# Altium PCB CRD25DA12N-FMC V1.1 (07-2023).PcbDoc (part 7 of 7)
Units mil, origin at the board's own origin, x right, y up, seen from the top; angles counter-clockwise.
Board outline 8000 x 8000 mil, 6 copper layers (Top Layer, Layer 2, Layer 3, Layer 4, Layer 5, Bottom Layer), stack 91 mil thick; 542 components, 315 nets, 1585 pads, 558 vias.
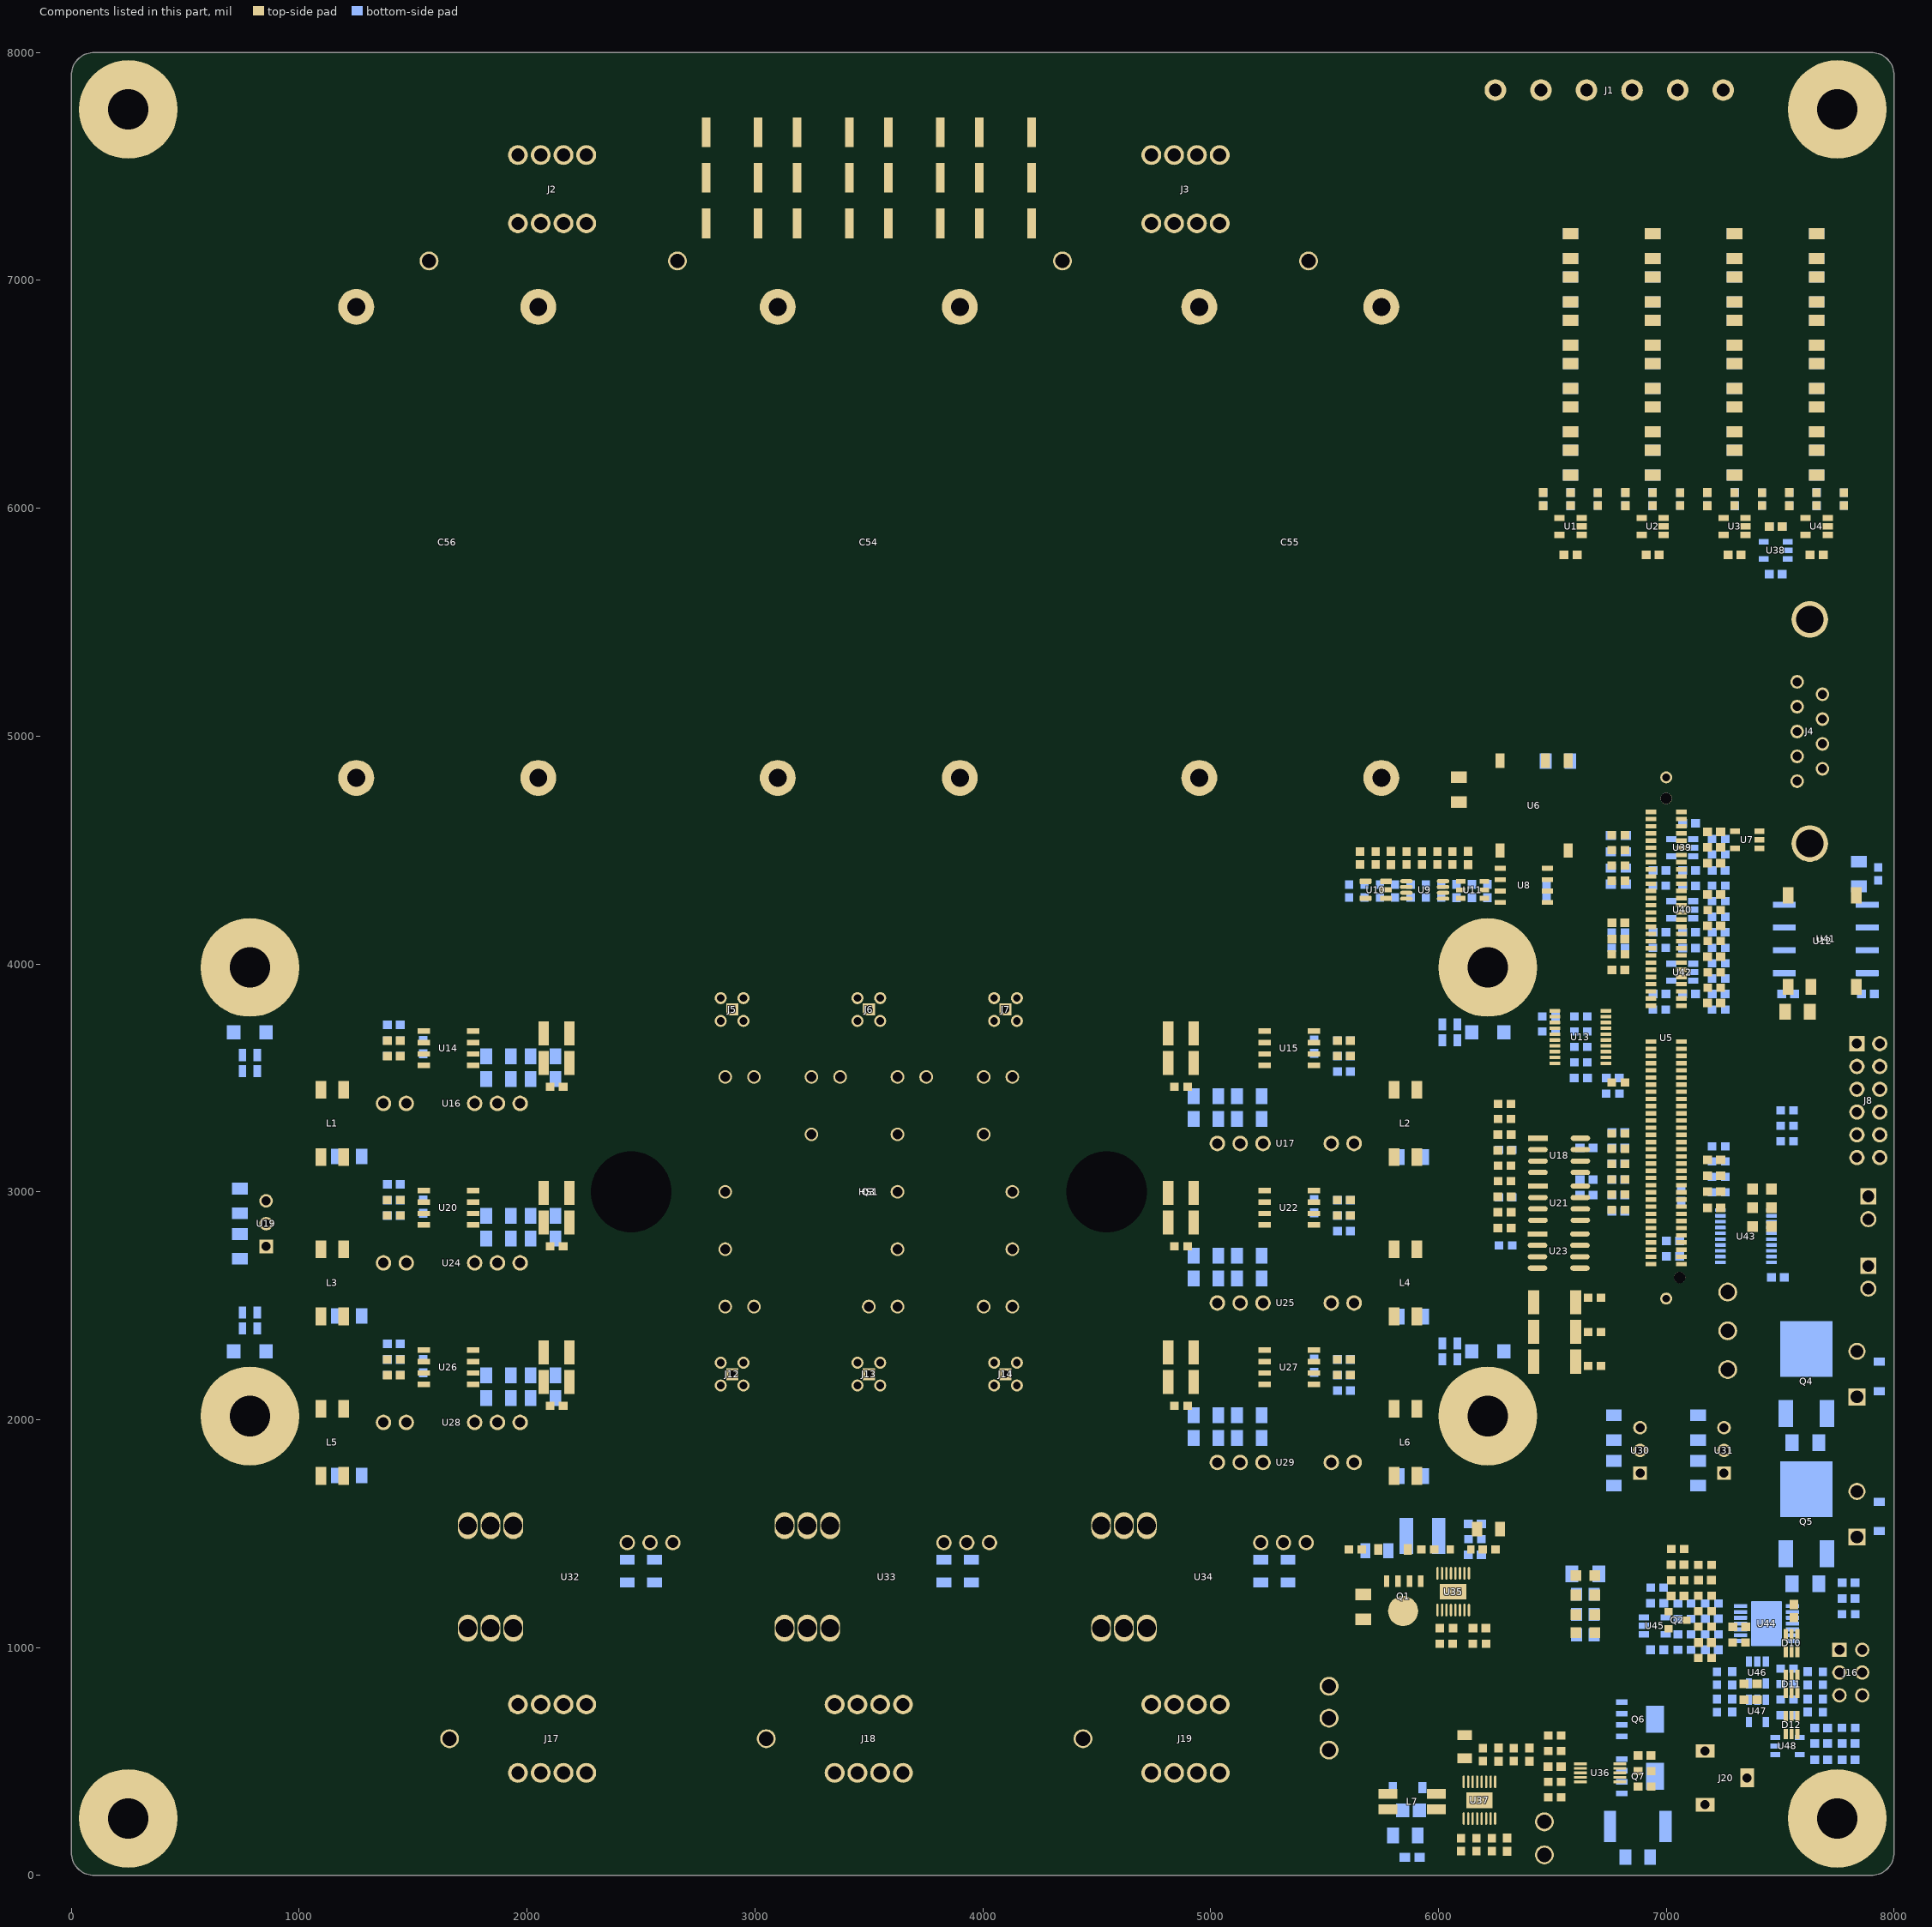
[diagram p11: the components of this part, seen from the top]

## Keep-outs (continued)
Layer 4:
  circle w10: c5040,7550 r200
  circle w10: c4740,7550 r200
  circle w10: c4740,7250 r200
  circle w10: c5040,7250 r200
  circle w10: c2850,3850 r190
  circle w10: c2850,3503.94 r190
  circle w10: c4150,3850 r190
  circle w10: c4150,3503.94 r190
  circle w10: c6065,7280 r192
  circle w10: c5670,4820 r235
  region: 4625,1490 4585,1490 4585,1420 4625,1420
  rectangle: 4265,985 4305,1055
  rectangle: 4535,7262.91 5245,7802.91
  region: 4555,7755 4515,7755 4515,7685 4555,7685
  rectangle: 4735,7044.79 5040,7077.21
  region: 5220,7750 5220,7710 5290,7710 5290,7750
  rectangle: 7724.19,4275 7783.78,4418.29
  region: 1415.31,1894.07 1415.31,1854.07 1485.31,1854.07 1485.31,1894.07
  rectangle: 2541.38,1103.21 2581.38,1173.21
  rectangle: 2800,260 2840,330
  rectangle: 3920,260 3960,330
  rectangle: 3931.38,1103.21 3971.38,1173.21
  rectangle: 4195,255 4235,325
  rectangle: 5317.18,1103.22 5357.18,1173.22
  rectangle: 5305,260 5345,330
  rectangle: 7455.41,5521.71 7515,5665
  rectangle: 7455.79,4364.18 7515.39,4507.46
  rectangle: 7734.19,3725 7793.78,3868.29
  rectangle: 7524,30 7654,255
  rectangle: 7754,331.5 7970,476.5
  rectangle: 7825,40 7960,165
  region: 4890,1395 4850,1395 4850,1325 4890,1325
  region: 4895,990 4895,1030 4825,1030 4825,990
  region: 3570,985 3570,1025 3500,1025 3500,985
  rectangle: 2920,980 2960,1050
  region: 2180,990 2180,1030 2110,1030 2110,990
  rectangle: 1530,985 1570,1055
  region: 1530,1665 1530,1625 1600,1625 1600,1665
  rectangle: 5930,4819.65 6047.21,4990.03
  rectangle: 5670,4965 6260,5060.38
  rectangle: 2656.25,3503.94 4345.42,3875.51
  rectangle: 2850,3310.19 4175.51,4045.42
  rectangle: 2335,3170 2375,3240
  rectangle: 1980,3170 2345,3295
  region: 4545,3165 4545,3205 4475,3205 4475,3165
  rectangle: 4530,3150 4735,3945
  rectangle: 2270.5,3210 2345.5,3845
  region: 5875,7755 5835,7755 5835,7685 5875,7685
  rectangle: 5867.58,7280 6120,7755
  rectangle: 6065,7082.58 6250,7755
  rectangle: 5630,4880 5705,5050.38
  rectangle: 5565,4860 5640,5030.38
  rectangle: 5530,4835 5605,5005.38
  rectangle: 5455,4750 5530,4920.38
  rectangle: 5495,4800 5570,4970.38
  rectangle: 6005,7095 6080,7265.38
  rectangle: 5945,7125 6020,7295.38
  region: 6250,7095 6210,7095 6210,7025 6250,7025
  region: 6255,5050 6255,5090 6185,5090 6185,5050
  rectangle: 5905,7165 5980,7335.38
  region: 4610,4020 4570,4020 4570,3950 4610,3950
  region: 4580,3990 4540,3990 4540,3920 4580,3920
  rectangle: 4659.34,3790 5435,4070.5
  region: 4675,4065 4635,4065 4635,3995 4675,3995
  region: 4635,4045 4595,4045 4595,3975 4635,3975
  rectangle: 1095,3856 2195,3971
  rectangle: 2165,3855 2240,3960
  region: 2290,3930 2215,3930 2215,3825 2290,3825
  region: 2270,3950 2195,3950 2195,3845 2270,3845
  region: 2320,3890 2245,3890 2245,3785 2320,3785
  region: 2310,3910 2235,3910 2235,3805 2310,3805
  region: 730,7745 730,7705 800,7705 800,7745
  rectangle: 5430,3975 5530,4820
  lines w10: 485,1750 ccw(c560,1750) 560,1675 ; 485.01,3653.79 cw(c560,3655) 558.79,3729.99 ; 753.02,4471.01 ccw(c878,4469) 875.99,4344.02 ; 755.02,7597.41 cw(c905,7595) 907.41,7744.98 ; 1147.85,4063.45 ccw(c1270,4090) 1267.99,3965.02 ; 1325,1675 ccw(c1325,1750) 1400,1750 ; 1400,1843.79 cw(c1474.99,1845) 1473.78,1919.99 ; 1503.79,3730.03 cw(c1505,3655.04) 1579.99,3656.25 ; 1506.21,1920.05 ccw(c1505,1995.04) 1579.99,1996.25 ; 1540,1145 ccw(c1690,1145) 1690,995 ; 1540.02,1512.41 cw(c1690,1510) 1692.41,1659.98 ; 1729.2,1969.19 ccw(c1779.2,1969.99) 1780,1920 ; 1729.2,2669.19 ccw(c1779.2,2669.99) 1780,2620 ; 1729.2,3369.19 ccw(c1779.2,3369.99) 1780,3320 ; 1730.01,2334.2 cw(c1780,2335) 1779.2,2384.99 ; 1730.01,3034.2 cw(c1780,3035) 1779.2,3084.99 ; 1730.01,3734.2 cw(c1780,3735) 1779.2,3784.99 ; 2020,995 ccw(c2020,1145) 2170,1145 ; 2124.95,3936.6 cw(c2208,3834) 2268.9,3716.89 ; 2199.2,2384.99 cw(c2200,2335) 2249.99,2335.8 ; 2199.2,3084.99 cw(c2200,3035) 2249.99,3035.8 ; 2199.2,3784.99 cw(c2200,3735) 2249.99,3735.8 ; 2200.8,1920.01 ccw(c2200,1970) 2249.99,1970.8 ; 2200.8,2620.01 ccw(c2200,2670) 2249.99,2670.8 ; 2200.8,3320.01 ccw(c2200,3370) 2249.99,3370.8 ; 2340.02,3332.41 ccw(c2490,3330) 2487.59,3180.02 ; 2380.01,1443.79 cw(c2455,1445) 2453.79,1519.99 ; 2544.2,1184.99 cw(c2545,1135) 2594.99,1135.8 ; 2595.01,118.79 ccw(c2670,120) 2671.21,45.01 ; 2703.79,1519.99 cw(c2705,1445) 2779.99,1446.21 ; 2780.01,313.79 ccw(c2855,315) 2856.21,240.01 ; 2858.39,2640 ccw(c2860,2739.99) 2959.99,2738.38 ; 2861.61,2849.99 cw(c2860,2750) 2959.99,2748.39 ; 2930,1145 ccw(c3080,1145) 3080,995 ; 3410,995 ccw(c3410,1145) 3560,1145 ; 3614.3,2640 ccw(c3615.91,2739.99) 3715.89,2738.38 ; 3617.51,2849.99 cw(c3615.91,2750) 3715.89,2748.39 ; 3770.01,1443.79 cw(c3845,1445) 3843.79,1519.99 ; 3911.21,240.01 ccw(c3910,315) 3984.99,316.21 ; 3934.2,1184.99 cw(c3935,1135) 3984.99,1135.8 ; 4041.62,2741.6 ccw(c4141.61,2739.99) 4140,2640 ; 4041.62,2751.62 cw(c4141.61,2750.01) 4143.22,2850 ; 4093.79,1519.99 cw(c4095,1445) 4169.99,1446.21 ; 4170.01,313.79 ccw(c4245,315) 4246.21,240.01 ; 4275,1145 ccw(c4425,1145) 4425,995 ; 4382.59,3180.02 ccw(c4385,3330) 4534.98,3327.59 ; 4394.41,7744.98 cw(c4392,7595) 4541.98,7592.59 ; 4535,1535 ccw(c4685,1535) 4685,1385 ; 4535.02,3942.03 cw(c4660,3940.02) 4662.01,4065 ; 4735,995 ccw(c4735,1145) 4885,1145 ; 4735,1385 cw(c4735,1235) 4885,1235 ; 4739.2,2325.81 cw(c4789.2,2325.01) 4790,2375 ; 4739.2,3025.81 cw(c4789.2,3025.01) 4790,3075 ; 4739.2,3725.81 cw(c4789.2,3725.01) 4790,3775 ; 4740.81,1820.8 ccw(c4790.8,1819.99) 4790,1770 ; 4740.81,2520.8 ccw(c4790.8,2519.99) 4790,2470 ; 4740.81,3220.8 ccw(c4790.8,3219.99) 4790,3170 ; 5104.2,2375.01 cw(c5104.2,2325.01) 5151.18,2342.11 ; 5104.2,3075.01 cw(c5104.2,3025.01) 5151.18,3042.11 ; 5104.2,3775.01 cw(c5104.2,3725.01) 5151.18,3742.11 ; 5160.01,1443.79 cw(c5235,1445) 5233.79,1519.99 ; 5220,1770 ccw(c5220.8,1819.99) 5270.8,1819.19 ; 5220,2470 ccw(c5220.8,2519.99) 5270.8,2519.19 ; 5220,3170 ccw(c5220.8,3219.99) 5270.8,3219.19 ; 5232.94,2313.3 cw(c5220,2265) 5270,2265 ; 5232.94,3013.3 cw(c5220,2965) 5270,2965 ; 5232.94,3713.3 cw(c5220,3665) 5270,3665 ; 5240.02,7597.41 cw(c5390,7595) 5392.41,7744.98 ; 5296.21,240.01 ccw(c5295,315) 5369.99,316.21 ; 5307.99,4065.02 ccw(c5310,4190) 5434.98,4187.99 ; 5320,1185 cw(c5320.8,1135.01) 5370.8,1135.81 ; 5320.81,1519.2 ccw(c5320.01,1569.2) 5370,1570 ; 5370,1575 cw(c5419.99,1575.8) 5419.19,1625.8 ; 5420.01,1733.79 ccw(c5495,1735) 5496.21,1660.01 ; 5420.01,3693.79 cw(c5495,3695) 5493.79,3769.99 ; 5580.01,4280.8 ccw(c5630,4279.99) 5629.2,4230 ; 5580.01,4475.8 cw(c5630,4475) 5630.8,4524.99 ; 5724.41,7744.98 cw(c5722,7595) 5871.98,7592.59 ; 5873.79,1624.99 cw(c5875,1550) 5949.99,1551.21 ; 5876.21,45.01 ccw(c5875,120) 5949.99,121.21 ; 5965.01,118.79 ccw(c6040,120) 6041.21,45.01 ; 5965.01,1548.79 cw(c6040,1550) 6038.79,1624.99 ; 6000,4524.53 ccw(c6000.8,4574.52) 6050.8,4573.71 ; 6050.01,4880.8 cw(c6100,4880) 6100.8,4929.99 ; 6088.79,3769.99 cw(c6090,3695) 6164.99,3696.21 ; 6091.21,1660.01 ccw(c6090,1735) 6164.99,1736.21 ; 6092.59,5055.02 ccw(c6095,5205) 6244.98,5202.59 ; 6097.41,7086.98 cw(c6095,6937) 6244.98,6934.59 ; 6111.21,1625.01 ccw(c6110,1700) 6184.99,1701.21 ; 6185.01,2308.79 ccw(c6260,2310) 6261.21,2235.01 ; 6185.01,3693.79 cw(c6260,3695) 6258.79,3769.99 ; 6186.22,1723.8 cw(c6261.21,1725.01) 6260,1800 ; 6249.2,4230.01 ccw(c6250,4280) 6299.99,4279.2 ; 6250.8,4929.99 cw(c6250,4880) 6299.99,4879.2 ; 6331.21,3770.01 ccw(c6330,3845) 6404.99,3846.21 ; 6405.01,6103.79 cw(c6480,6105) 6478.79,6179.99 ; 6531.21,45.01 ccw(c6530,120) 6604.99,121.21 ; 6605.01,118.79 ccw(c6680,120) 6681.21,45.01 ; 6605,530 cw(c6680,530) 6680,605 ; 7315,605 cw(c7315,530) 7390,530 ; 7316.21,45.01 ccw(c7315,120) 7389.99,121.21 ccw(c7464.98,122.41) 7466.19,47.42 ; 7335,1945 ccw(c7360,1945) 7360,1920 ; 7335,1970 cw(c7360,1970) 7360,1995 ; 7420,580 ccw(c7445,580) 7445,555 ; 7420,685 cw(c7445,685) 7445,710 ; 7435.01,4418.79 ccw(c7510,4420) 7511.21,4345.01 ; 7435.01,5608.79 cw(c7510,5610) 7508.79,5684.99 ; 7456.21,47.42 ccw(c7455,122.41) 7529.99,123.62 ; 7500,710 ccw(c7500,735) 7525,735 ; 7500,1920 cw(c7500,1895) 7525,1895 ; 7535.01,4686.79 ccw(c7610,4688) 7611.21,4613.01 ; 7535.01,5351.79 cw(c7610,5353) 7608.79,5427.99 ; 7545,1995 cw(c7545,1970) 7570,1970 ; 7570,650 ccw(c7595,650) 7595,625 ; 7605,555 ccw(c7605,580) 7630,580 ; 7605,625 cw(c7605,600) 7630,600 ; 7633.79,4344.99 cw(c7635,4270) 7709.99,4271.21 ; 7710.01,3778.79 ccw(c7785,3780) 7786.21,3705.01 ; 7710.01,4491.12 ccw(c7765,4492) 7765.88,4437.01 ; 7715.01,5523.79 cw(c7790,5525) 7788.79,5599.99 ; 7749.12,4439.99 cw(c7750,4385) 7804.99,4385.88 ; 7805.01,3889.2 ccw(c7855,3890) 7855.8,3840.01 ; 7878.79,5599.99 cw(c7880,5525) 7954.99,5526.21 ; 7878.79,6179.99 cw(c7880,6105) 7954.99,6106.21 ; 7881.21,469.93 ccw(c7880,544.92) 7954.99,546.13 ; 7881.21,5685.01 ccw(c7880,5760) 7954.99,5761.21 ; 7883.79,3704.99 cw(c7885,3630) 7959.99,3631.21 ; 7905.81,3839.2 ccw(c7905.01,3889.2) 7955,3890
Layer 5:
  circle w10: c1960,7550 r200
  circle w10: c1960,7250 r200
  circle w10: c2260,7550 r200
  circle w10: c2260,7250 r200
  circle w10: c2850,3850 r190
  circle w10: c2850,3503.94 r190
  circle w10: c4150,3503.94 r190
  circle w10: c4150,3850 r190
  circle w10: c6065,7280 r192
  rectangle: 1625,3460 1725,3808.71
  region: 1132.42,4041.06 1072.42,4041.06 1072.42,3826.06 1132.42,3826.06
  region: 1843.21,6875 1843.21,7180 1810.79,7180 1810.79,6875
  region: 2289.21,6875 2289.21,7180 2256.79,7180 2256.79,6875
  region: 1601.27,6999.57 1359.3,6813.89 1428.03,6724.33 1670,6910
  region: 1445.61,7242.78 1171.71,7108.6 1221.38,7007.22 1495.28,7141.4
  rectangle: 3237.88,3061.97 4005,3330
  rectangle: 1755,7262.91 2465,7802.91
  region: 1775,7755 1735,7755 1735,7685 1775,7685
  region: 2440,7750 2440,7710 2510,7710 2510,7750
  rectangle: 1955,7044.79 2260,7077.21
  rectangle: 7734.19,3725 7793.78,3868.29
  rectangle: 7455.79,4364.18 7515.39,4507.46
  region: 1415.31,1894.07 1415.31,1854.07 1485.31,1854.07 1485.31,1894.07
  rectangle: 5317.18,1103.22 5357.18,1173.22
  rectangle: 5365,1545 5405,1615
  rectangle: 5305,260 5345,330
  rectangle: 4195,255 4235,325
  rectangle: 7455.41,5521.71 7515,5665
  rectangle: 7724.19,4275 7783.78,4418.29
  rectangle: 2541.38,1103.21 2581.38,1173.21
  rectangle: 3931.38,1103.21 3971.38,1173.21
  rectangle: 2800,260 2840,330
  rectangle: 3920,260 3960,330
  rectangle: 5990,3975 6080,4120
  rectangle: 7524,30 7654,255
  rectangle: 7754,331.5 7970,476.5
  rectangle: 7825,40 7960,165
  region: 4310,1625 4310,1585 4380,1585 4380,1625
  region: 4955,1630 4915,1630 4915,1560 4955,1560
  rectangle: 4315,325 4355,395
  region: 5250,330 5250,370 5180,370 5180,330
  region: 2920,1630 2920,1590 2990,1590 2990,1630
  region: 3565,1635 3525,1635 3525,1565 3565,1565
  rectangle: 2925,325 2965,395
  region: 3860,330 3860,370 3790,370 3790,330
  region: 2470,330 2470,370 2400,370 2400,330
  rectangle: 1535,325 1575,395
  region: 2175,1635 2135,1635 2135,1565 2175,1565
  region: 1530,1630 1530,1590 1600,1590 1600,1630
  rectangle: 5342.08,3758.41 5401.67,3901.7
  rectangle: 5260.61,3920 5485,3995
  rectangle: 5385.61,4025 5580,4078.37
  rectangle: 5445.61,4060 5635,4113.37
  rectangle: 5360,3835 5429.94,4055
  rectangle: 5415,4105 5550,4125
  rectangle: 5380,3985 5545,4088.29
  rectangle: 5304.19,3670 5363.78,3813.29
  rectangle: 2656.25,3503.94 4345.42,3875.51
  rectangle: 2850,3310.19 4175.51,4045.42
  region: 730,7745 730,7705 800,7705 800,7745
  rectangle: 2270.5,3225 2345.5,3845
  region: 2320,3890 2245,3890 2245,3785 2320,3785
  region: 2270,3950 2195,3950 2195,3845 2270,3845
  rectangle: 1095,3856 2195,3971
  region: 2310,3910 2235,3910 2235,3805 2310,3805
  region: 2290,3930 2215,3930 2215,3825 2290,3825
  rectangle: 2165,3855 2240,3960
  region: 875,4325 705,4325 705,4255 875,4255
  region: 980,4275 810,4275 810,4205 980,4205
  region: 1110,4115 1050,4115 1050,3900 1110,3900
  region: 1060,4200 1000,4200 1000,3985 1060,3985
  region: 1000,4255 940,4255 940,4155 1000,4155
  rectangle: 1150,3800 1725,3894.7
  rectangle: 1780,3090 2345,3295
  region: 5875,7755 5835,7755 5835,7685 5875,7685
  rectangle: 5867.58,7280 6120,7755
  rectangle: 6065,7082.58 6250,7755
  rectangle: 5945,7125 6020,7295.38
  rectangle: 5905,7165 5980,7335.38
  rectangle: 6005,7095 6080,7265.38
  region: 6250,7095 6210,7095 6210,7025 6250,7025
  rectangle: 2755,3340 2855,3465
  rectangle: 2675,3430 2775,3555
  rectangle: 2705,3380 2805,3505
  region: 2736.06,4000.08 2736.06,3900.08 2861.06,3900.08 2861.06,4000.08
  region: 2786.06,4030.08 2786.06,3930.08 2911.06,3930.08 2911.06,4030.08
  region: 2696.06,3950.08 2696.06,3850.08 2821.06,3850.08 2821.06,3950.08
  region: 4295,3505 4195,3505 4195,3380 4295,3380
  region: 4325,3555 4225,3555 4225,3430 4325,3430
  region: 4245,3465 4145,3465 4145,3340 4245,3340
  region: 4178.94,3950.08 4178.94,3850.08 4303.94,3850.08 4303.94,3950.08
  region: 4088.94,4030.08 4088.94,3930.08 4213.94,3930.08 4213.94,4030.08
  region: 4138.94,4000.08 4138.94,3900.08 4263.94,3900.08 4263.94,4000.08
  rectangle: 2335,3170 2375,3240
  rectangle: 2270,2870 2340,3122.06
  rectangle: 5590,4537.97 6040,4680
  rectangle: 5650,4132.97 6070,4215
  rectangle: 5895,4568.58 6044.8,4925
  rectangle: 6060,4933.58 6390,5085
  rectangle: 5425,4120 5568.9,4520
  rectangle: 5545,4115 5810,4185
  rectangle: 5925,4930 6345,5007.03
  rectangle: 5445,4497.97 5540,4580
  rectangle: 5997.36,4986.83 6390,5063.86
  rectangle: 5476.9,4548.76 5571.9,4630.79
  rectangle: 5530,4582.97 5625,4665
  rectangle: 5850,4645 5920,4722.03
  rectangle: 6190,5050 6260,5127.03
  rectangle: 4530,3070 4745,3945
  region: 4580,3990 4540,3990 4540,3920 4580,3920
  region: 4610,4020 4570,4020 4570,3950 4610,3950
  region: 4635,4045 4595,4045 4595,3975 4635,3975
  region: 4675,4065 4635,4065 4635,3995 4675,3995
  rectangle: 4659.34,3790 5370,4070.5
  lines w10: 433.64,3984.25 cw(c783.46,3984.25) 1133.29,3984.25 ; 485,1750 ccw(c560,1750) 560,1675 ; 485.01,3653.79 cw(c560,3655) 558.79,3729.99 ; 755.02,4450.01 ccw(c880,4448) 877.99,4323.02 ; 755.02,7597.41 cw(c905,7595) 907.41,7744.98 ; 1122.85,4063.45 ccw(c1245,4090) 1242.99,3965.02 ; 1325,1675 ccw(c1325,1750) 1400,1750 ; 1400,1843.79 cw(c1474.99,1845) 1473.78,1919.99 ; 1502.78,3729.23 cw(c1503.99,3654.24) 1578.98,3655.45 ; 1505.19,1919.25 ccw(c1503.99,1994.24) 1578.98,1995.45 ; 1540.02,487.41 ccw(c1690,485) 1687.59,335.02 ; 1540.02,1477.41 cw(c1690,1475) 1692.41,1624.98 ; 1614.41,7744.98 cw(c1612,7595) 1761.98,7592.59 ; 1730,2167 ccw(c1780,2167) 1762.9,2120.02 ; 1730,2265 cw(c1780,2265) 1780,2315 1805,2315 ; 1730,2867 ccw(c1780,2867) 1762.9,2820.02 ; 1730,2965 cw(c1780,2965) 1780,3015 1805,3015 ; 1730,3567 ccw(c1780,3567) 1762.9,3520.02 ; 1730,3665 cw(c1780,3665) 1780,3715 1805,3715 ; 1781.32,2069.24 ccw(c1828.3,2052.14) 1790,2020 ; 1781.32,2769.24 ccw(c1828.3,2752.14) 1790,2720 ; 1781.32,3469.24 ccw(c1828.3,3452.14) 1790,3420 ; 1804.2,1969.19 ccw(c1854.2,1969.99) 1855,1920 ; 1804.2,2669.19 ccw(c1854.2,2669.99) 1855,2620 ; 1804.2,3369.19 ccw(c1854.2,3369.99) 1855,3320 ; 1849.01,2334.2 cw(c1899,2335) 1898.2,2384.99 ; 1849.01,3034.2 cw(c1899,3035) 1898.2,3084.99 ; 1849.01,3734.2 cw(c1899,3735) 1898.2,3784.99 ; 2022.41,1624.98 cw(c2020,1475) 2169.98,1472.59 ; 2124.95,3936.6 cw(c2208,3834) 2268.9,3716.89 ; 2199.2,2384.99 cw(c2200,2335) 2249.99,2335.8 ; 2199.2,3084.99 cw(c2200,3035) 2249.99,3035.8 ; 2199.2,3784.99 cw(c2200,3735) 2249.99,3735.8 ; 2200.8,1920.01 ccw(c2200,1970) 2249.99,1970.8 ; 2200.8,2620.01 ccw(c2200,2670) 2249.99,2670.8 ; 2200.8,3320.01 ccw(c2200,3370) 2249.99,3370.8 ; 2285,6947 cw(c2435,6947) 2360,7076.9 ; 2307.59,335.02 ccw(c2310,485) 2459.98,482.59 ; 2340.02,3332.41 ccw(c2490,3330) 2487.59,3180.02 ; 2380.01,1443.79 cw(c2455,1445) 2453.79,1519.99 ; 2460.02,7597.41 cw(c2610,7595) 2612.41,7744.98 ; 2544.2,1184.99 cw(c2545,1135) 2594.99,1135.8 ; 2595.01,118.79 ccw(c2670,120) 2671.21,45.01 ; 2633.02,3052.01 ccw(c2758,3050) 2755.99,2925.02 ; 2703.79,1519.99 cw(c2705,1445) 2779.99,1446.21 ; 2780.01,313.79 ccw(c2855,315) 2856.21,240.01 ; 2930.02,487.41 ccw(c3080,485) 3077.59,335.02 ; 2930.02,1477.41 cw(c3080,1475) 3082.41,1624.98 ; 2986.79,3315.99 cw(c2988,3241) 3062.99,3242.21 ; 3412.41,1624.98 cw(c3410,1475) 3559.98,1472.59 ; 3697.59,335.02 ccw(c3700,485) 3849.98,482.59 ; 3770.01,1443.79 cw(c3845,1445) 3843.79,1519.99 ; 3911.21,240.01 ccw(c3910,315) 3984.99,316.21 ; 3934.2,1184.99 cw(c3935,1135) 3984.99,1135.8 ; 4093.79,1519.99 cw(c4095,1445) 4169.99,1446.21 ; 4170.01,313.79 ccw(c4245,315) 4246.21,240.01 ; 4189,3265 cw(c4264,3265) 4238.35,3335.48 ; 4244.01,2925.02 ccw(c4242,3050) 4366.98,3052.01 ; 4320.02,487.41 ccw(c4470,485) 4467.59,335.02 ; 4320.02,1472.41 cw(c4470,1470) 4472.41,1619.98 ; 4455,3159.32 ccw(c4410.15,3276) 4535.13,3273.99 ; 4535.02,3942.03 cw(c4660,3940.02) 4662.01,4065 ; 4739.2,2325.81 cw(c4789.2,2325.01) 4790,2375 ; 4739.2,3025.81 cw(c4789.2,3025.01) 4790,3075 ; 4740,3725 cw(c4790,3725) 4790,3775 ; 4740.81,1820.8 ccw(c4790.8,1819.99) 4790,1770 ; 4740.81,2520.8 ccw(c4790.8,2519.99) 4790,2470 ; 4740.81,3220.8 ccw(c4790.8,3219.99) 4790,3170 ; 4802.41,1619.98 cw(c4800,1470) 4949.98,1467.59 ; 5087.59,335.02 ccw(c5090,485) 5239.98,482.59 ; 5104.2,2375.01 cw(c5104.2,2325.01) 5151.18,2342.11 ; 5104.2,3075.01 cw(c5104.2,3025.01) 5151.18,3042.11 ; 5104.2,3775.01 cw(c5104.2,3725.01) 5151.18,3742.11 ; 5160.01,1443.79 cw(c5235,1445) 5233.79,1519.99 ; 5220,1770 ccw(c5220.8,1819.99) 5270.8,1819.19 ; 5220,2470 ccw(c5220.8,2519.99) 5270.8,2519.19 ; 5220,3170 ccw(c5220.8,3219.99) 5270.8,3219.19 ; 5232.94,2313.3 cw(c5220,2265) 5270,2265 ; 5232.94,3013.3 cw(c5220,2965) 5270,2965 ; 5232.94,3713.3 cw(c5220,3665) 5270,3665 ; 5296.21,240.01 ccw(c5295,315) 5369.99,316.21 ; 5307.99,4065.02 ccw(c5310,4190) 5434.98,4187.99 ; 5320,1185 cw(c5320.8,1135.01) 5370.8,1135.81 ; 5345,1520 ccw(c5343.79,1594.99) 5418.78,1596.2 ; 5418.62,3711.49 cw(c5818.56,3705.05) 5825,4105 ; 5430.02,4517.57 cw(c5590,4515) 5592.57,4674.98 ; 5580.01,4280.8 ccw(c5630,4279.99) 5629.2,4230 ; 5580.01,4475.8 cw(c5630,4475) 5630.8,4524.99 ; 5724.41,7744.98 cw(c5722,7595) 5871.98,7592.59 ; 5747.59,4675.02 ccw(c5750,4825) 5899.98,4822.59 ; 5900.02,4922.59 cw(c6060,4920.02) 6062.57,5080 ; 5918.79,4104.99 cw(c5920,4030) 5994.99,4031.21 ; 6000,4524.53 ccw(c6000.8,4574.52) 6050.8,4573.71 ; 6050.01,4880.8 cw(c6100,4880) 6100.8,4929.99 ; 6089.59,5080.02 ccw(c6092,5230) 6241.98,5227.59 ; 6097.41,7086.98 cw(c6095,6937) 6244.98,6934.59 ; 6249.2,4230.01 ccw(c6250,4280) 6299.99,4279.2 ; 6250.8,4929.99 cw(c6250,4880) 6299.99,4879.2 ; 6405.01,6103.79 cw(c6480,6105) 6478.79,6179.99 ; 7435.01,4418.79 ccw(c7510,4420) 7511.21,4345.01 ; 7435.01,5608.79 cw(c7510,5610) 7508.79,5684.99 ; 7456.21,45.01 ccw(c7455,120) 7529.99,121.21 ; 7535.01,4513.79 ccw(c7610,4515) 7611.21,4440.01 ; 7535.01,5523.79 cw(c7610,5525) 7608.79,5599.99 ; 7633.8,4343.78 cw(c7635.01,4268.79) 7710,4270 ; 7710.01,3778.79 ccw(c7785,3780) 7786.21,3705.01 ; 7728.79,4439.99 cw(c7730,4365) 7804.99,4366.21 ; 7805.01,3889.2 ccw(c7855,3890) 7855.8,3840.01 ; 7878.79,5599.99 cw(c7880,5525) 7954.99,5526.21 ; 7878.79,6179.99 cw(c7880,6105) 7954.99,6106.21 ; 7881.21,470.01 ccw(c7880,545) 7954.99,546.21 ; 7881.21,5685.01 ccw(c7880,5760) 7954.99,5761.21 ; 7883.79,3704.99 cw(c7885,3630) 7959.99,3631.21 ; 7905.81,3839.2 ccw(c7905.01,3889.2) 7955,3890
Bottom Layer:
  circle w10: c5040,7550 r200
  circle w10: c5040,7250 r200
  circle w10: c4740,7250 r200
  circle w10: c4740,7550 r200
  circle w10: c6065,7280 r192
  circle w10: c2850,3850 r190
  circle w10: c4150,3850 r190
  circle w10: c2850,3503.94 r190
  circle w10: c4150,3503.94 r190
  circle w10: c5670,4820 r235
  region: 4625,1490 4585,1490 4585,1420 4625,1420
  rectangle: 4659.34,3790 5435,4070.5
  rectangle: 4530,3150 4745,3945
  region: 3570,990 3570,1030 3500,1030 3500,990
  rectangle: 2923.73,985.09 2963.73,1055.09
  region: 5220,7750 5220,7710 5290,7710 5290,7750
  region: 4555,7755 4515,7755 4515,7685 4555,7685
  rectangle: 4735,7044.79 5040,7077.21
  rectangle: 4535,7262.91 5245,7802.91
  rectangle: 1533.73,985.46 1573.73,1055.46
  region: 2180,990.37 2180,1030.37 2110,1030.37 2110,990.37
  region: 4895,990 4895,1030 4825,1030 4825,990
  rectangle: 4268.73,985.09 4308.73,1055.09
  region: 4890,1395 4850,1395 4850,1325 4890,1325
  region: 1530,1665 1530,1625 1600,1625 1600,1665
  rectangle: 5675,4805 6000,4950.38
  region: 4545,3165 4545,3205 4475,3205 4475,3165
  region: 4675,4065 4635,4065 4635,3995 4675,3995
  region: 4635,4045 4595,4045 4595,3975 4635,3975
  region: 4610,4020 4570,4020 4570,3950 4610,3950
  region: 4580,3990 4540,3990 4540,3920 4580,3920
  rectangle: 2335,3170 2375,3240
  region: 6250,7095 6210,7095 6210,7025 6250,7025
  region: 5875,7755 5835,7755 5835,7685 5875,7685
  rectangle: 5905,7165 5980,7335.38
  rectangle: 5945,7125 6020,7295.38
  rectangle: 6005,7095 6080,7265.38
  rectangle: 5867.58,7280 6120,7755
  rectangle: 6065,7082.58 6250,7755
  rectangle: 1980,3170 2345,3295
  region: 2310,3910 2235,3910 2235,3805 2310,3805
  region: 2290,3930 2215,3930 2215,3825 2290,3825
  region: 2270,3950 2195,3950 2195,3845 2270,3845
  region: 2320,3890 2185,3890 2185,3785 2320,3785
  rectangle: 2165,3855 2240,3960
  rectangle: 2270.5,3285 2345.5,3845
  rectangle: 1095,3795 2235,3971
  region: 730,7740 730,7700 800,7700 800,7740
  rectangle: 2656.25,3503.94 4345.42,3875.51
  rectangle: 2850,3310.19 4175.51,4045.42
  rectangle: 5670,4950 6350,5060.38
  rectangle: 5495,4800 5570,4970.38
  rectangle: 5455,4750 5530,4920.38
  rectangle: 5530,4835 5605,5005.38
  rectangle: 5565,4860 5640,5030.38
  rectangle: 5630,4880 5705,5050.38
  region: 6255,5050 6255,5090 6185,5090 6185,5050
  rectangle: 5430,3975 6050,4820
  lines w10: 680,2680 ccw(c705,2680) 705,2655 ; 680,2735 cw(c705,2735) 705,2760 cw(c705,2785) 680,2785 ; 680,2935 cw(c705,2935) 705,2960 cw(c705,2985) 680,2985 ; 680,3040 cw(c705,3040) 705,3065 ; 753.02,4471.01 ccw(c878,4469) 875.99,4344.02 ; 755.02,7597.41 cw(c905,7595) 907.41,7744.98 ; 775,2760 ccw(c775,2785) 800,2785 cw(c825,2785) 825,2810 ; 775,2960 cw(c775,2935) 800,2935 ccw(c825,2935) 825,2910 ; 885,2655 ccw(c885,2680) 910,2680 ; 885,3065 cw(c885,3040) 910,3040 ; 910,2785 ccw(c885,2785) 885,2810 ccw(c885,2835) 910,2835 ; 910,2885 ccw(c885,2885) 885,2910 ccw(c885,2935) 910,2935 ; 1040,1720 ccw(c1090,1720) 1090,1670 ; 1040.01,1891.2 cw(c1090,1892) 1089.2,1941.99 ; 1040,2420 ccw(c1090,2420) 1090,2370 ; 1040.01,2591.2 cw(c1090,2592) 1089.2,2641.99 ; 1040,3120 ccw(c1090,3120) 1090,3070 ; 1040.01,3291.2 cw(c1090,3292) 1089.2,3341.99 ; 1147.85,4063.45 ccw(c1270,4090) 1267.99,3965.02 ; 1170,1675 ccw(c1170,1725) 1220,1725 ccw(c1270,1725) 1270,1675 ; 1170,2375 ccw(c1170,2425) 1220,2425 ccw(c1270,2425) 1270,2375 ; 1170,3075 ccw(c1170,3125) 1220,3125 ccw(c1270,3125) 1270,3075 ; 1190,1945 ccw(c1190,1995) 1240,1995 cw(c1290,1995) 1290,2045 ; 1190,2645 ccw(c1190,2695) 1240,2695 cw(c1290,2695) 1290,2745 ; 1190,3345 ccw(c1190,3395) 1240,3395 cw(c1290,3395) 1290,3445 ; 1220,1795 cw(c1270,1795) 1270,1845 ; 1220,2495 cw(c1270,2495) 1270,2545 ; 1220,3195 cw(c1270,3195) 1270,3245 ; 1350,1845 cw(c1350,1795) 1400,1795 ; 1350,2545 cw(c1350,2495) 1400,2495 ; 1350,3245 cw(c1350,3195) 1400,3195 ; 1350.81,1674.2 ccw(c1350.01,1724.2) 1400,1725 ; 1350.81,2374.2 ccw(c1350.01,2424.2) 1400,2425 ; 1350.81,3074.2 ccw(c1350.01,3124.2) 1400,3125 ; 1355,1845 ccw(c1355,1895) 1401.98,1877.9 ; 1355,2545 ccw(c1355,2595) 1401.98,2577.9 ; 1355,3245 ccw(c1355,3295) 1401.98,3277.9 ; 1400.01,1869.2 cw(c1450,1870) 1449.2,1919.99 ; 1400.01,2569.2 cw(c1450,2570) 1449.2,2619.99 ; 1400.01,3269.2 cw(c1450,3270) 1449.2,3319.99 ; 1479.2,2044.99 cw(c1480,1995) 1529.99,1995.8 ; 1479.2,2744.99 cw(c1480,2695) 1529.99,2695.8 ; 1479.2,3444.99 cw(c1480,3395) 1529.99,3395.8 ; 1480.8,1920.01 ccw(c1480,1970) 1529.99,1970.8 ; 1480.8,2620.01 ccw(c1480,2670) 1529.99,2670.8 ; 1480.8,3320.01 ccw(c1480,3370) 1529.99,3370.8 ; 1538.75,1147.87 ccw(c1688.73,1145.46) 1686.32,995.48 ; 1540.02,1512.41 cw(c1690,1510) 1692.41,1659.98 ; 1730,1970 ccw(c1780,1970) 1780,1920 ; 1730,2335 cw(c1780,2335) 1780,2385 ; 1730,2670 ccw(c1780,2670) 1780,2620 ; 1730,3035 cw(c1780,3035) 1780,3085 ; 1730,3370 ccw(c1780,3370) 1780,3320 ; 1730,3735 cw(c1780,3735) 1780,3785 ; 1775,1920 ccw(c1775,1970) 1825,1970 ccw(c1875,1970) 1875,1920 ; 1775,2620 ccw(c1775,2670) 1825,2670 ccw(c1875,2670) 1875,2620 ; 1775,3320 ccw(c1775,3370) 1825,3370 ccw(c1875,3370) 1875,3320 ; 1825,2005 cw(c1850,2005) 1850,2030 ccw(c1850,2055) 1875,2055 ; 1825,2385 cw(c1825,2335) 1875,2335 cw(c1925,2335) 1925,2385 ; 1825,2705 cw(c1850,2705) 1850,2730 ccw(c1850,2755) 1875,2755 ; 1825,3085 cw(c1825,3035) 1875,3035 cw(c1925,3035) 1925,3085 ; 1825,3405 cw(c1850,3405) 1850,3430 ccw(c1850,3455) 1875,3455 ; 1825,3785 cw(c1825,3735) 1875,3735 cw(c1925,3735) 1925,3785 ; 1880,1920 ccw(c1880,1970) 1930,1970 ccw(c1980,1970) 1980,1920 ; 1880,2620 ccw(c1880,2670) 1930,2670 ccw(c1980,2670) 1980,2620 ; 1880,3320 ccw(c1880,3370) 1930,3370 ccw(c1980,3370) 1980,3320 ; 1930,1980 cw(c1980,1980) 1980,2030 ; 1930,2680 cw(c1980,2680) 1980,2730 ; 1930,3380 cw(c1980,3380) 1980,3430 ; 2017.59,995.39 ccw(c2020,1145.37) 2169.98,1142.96 ; 2025,2030 ccw(c2025,2080) 2075,2080 ; 2025,2385 cw(c2025,2335) 2075,2335 cw(c2125,2335) 2125,2385 ; 2025,2730 ccw(c2025,2780) 2075,2780 ; 2025,3085 cw(c2025,3035) 2075,3035 cw(c2125,3035) 2125,3085 ; 2025,3430 ccw(c2025,3480) 2075,3480 ; 2025,3785 cw(c2025,3735) 2075,3735 cw(c2125,3735) 2125,3785 ; 2124.95,3936.6 cw(c2208,3834) 2268.9,3716.89 ; 2200,1920 ccw(c2199.2,1969.99) 2249.19,1970.8 ; 2200,2385 cw(c2200.8,2335.01) 2250.8,2335.81 ; 2200,2620 ccw(c2199.2,2669.99) 2249.19,2670.8 ; 2200,3085 cw(c2200.8,3035.01) 2250.8,3035.81 ; 2200,3320 ccw(c2199.2,3369.99) 2249.19,3370.8 ; 2200,3785 cw(c2200.8,3735.01) 2250.8,3735.81 ; 2340.02,3332.41 ccw(c2490,3330) 2487.59,3180.02 ; 2858.39,2640 ccw(c2860,2739.99) 2959.99,2738.38 ; 2861.61,2849.99 cw(c2860,2750) 2959.99,2748.39 ; 2928.75,1147.5 ccw(c3078.73,1145.09) 3076.32,995.11 ; 3407.59,995.02 ccw(c3410,1145) 3559.98,1142.59 ; 3614.3,2640 ccw(c3615.91,2739.99) 3715.89,2738.38 ; 3617.51,2849.99 cw(c3615.91,2750) 3715.89,2748.39 ; 4041.62,2741.6 ccw(c4141.61,2739.99) 4140,2640 ; 4041.62,2751.62 cw(c4141.61,2750.01) 4143.22,2850 ; 4273.75,1147.5 ccw(c4423.73,1145.09) 4421.32,995.11 ; 4382.59,3180.02 ccw(c4385,3330) 4534.98,3327.59 ; 4394.41,7744.98 cw(c4392,7595) 4541.98,7592.59 ; 4535,1535 ccw(c4685,1535) 4685,1385 ; 4535.02,3942.03 cw(c4660,3940.02) 4662.01,4065 ; 4732.59,995.02 ccw(c4735,1145) 4884.98,1142.59 ; 4737.41,1384.98 cw(c4735,1235) 4884.98,1232.59 ; 4739.2,2325.81 cw(c4789.2,2325.01) 4790,2375 ; 4739.2,3025.81 cw(c4789.2,3025.01) 4790,3075 ; 4740.8,1819.99 ccw(c4790.8,1819.99) 4790.8,1769.99 ; 4740.8,2519.99 ccw(c4790.8,2519.99) 4790.8,2469.99 ; 4740.8,3219.99 ccw(c4790.8,3219.99) 4790.8,3169.99 ; 4775,3725 cw(c4825,3725) 4825,3775 ; 4970,1905 ccw(c5020,1905) 5020,1855 ; 4970,2100 cw(c5020,2100) 5020,2150 ; 4970,2605 ccw(c5020,2605) 5020,2555 ; 4970,2800 cw(c5020,2800) 5020,2850 ; 4970,3305 ccw(c5020,3305) 5020,3255 ; 4970,3500 cw(c5020,3500) 5020,3550 ; 5040,1770 ccw(c5040,1820) 5089.24,1811.32 ; 5040,1855 cw(c5040,1805) 5090,1805 ; 5040,2470 ccw(c5040,2520) 5089.24,2511.32 ; 5040,2555 cw(c5040,2505) 5090,2505 ; 5040,3170 ccw(c5040,3220) 5089.24,3211.32 ; 5040,3255 cw(c5040,3205) 5090,3205 ; 5088.76,1811.32 ccw(c5138,1820) 5138,1770 ; 5088.76,2511.32 ccw(c5138,2520) 5138,2470 ; 5088.76,3211.32 ccw(c5138,3220) 5138,3170 ; 5125,1770 ccw(c5125,1820) 5175,1820 ccw(c5225,1820) 5225,1770 ; 5125,2150 cw(c5125,2100) 5175,2100 cw(c5225,2100) 5225,2150 ; 5125,2470 ccw(c5125,2520) 5175,2520 ccw(c5225,2520) 5225,2470 ; 5125,2850 cw(c5125,2800) 5175,2800 cw(c5225,2800) 5225,2850 ; 5125,3170 ccw(c5125,3220) 5175,3220 ccw(c5225,3220) 5225,3170 ; 5125,3550 cw(c5125,3500) 5175,3500 cw(c5225,3500) 5225,3550 ; 5219.2,1770.81 ccw(c5220.01,1820.8) 5270,1820 ; 5219.2,2470.81 ccw(c5220.01,2520.8) 5270,2520 ; 5219.2,3170.81 ccw(c5220.01,3220.8) 5270,3220 ; 5220,2375 cw(c5219.2,2325.01) 5269.19,2324.2 ; 5220,3075 cw(c5219.2,3025.01) 5269.19,3024.2 ; 5220,3775 cw(c5219.2,3725.01) 5269.19,3724.2 ; 5240.02,7597.41 cw(c5390,7595) 5392.41,7744.98 ; 5270,2100 ccw(c5220,2100) 5220,2150 ccw(c5220,2200) 5270,2200 ; 5270,2800 ccw(c5220,2800) 5220,2850 ccw(c5220,2900) 5270,2900 ; 5270,3500 ccw(c5220,3500) 5220,3550 ccw(c5220,3600) 5270,3600 ; 5307.99,4065.02 ccw(c5310,4190) 5434.98,4187.99 ; 5475,1730 ccw(c5524.99,1730.8) 5525.8,1680.81 ; 5475,2430 ccw(c5524.99,2430.8) 5525.8,2380.81 ; 5475,3130 ccw(c5524.99,3130.8) 5525.8,3080.81 ; 5475.81,1849.2 cw(c5525.8,1850.01) 5525,1900 ; 5475.81,2549.2 cw(c5525.8,2550.01) 5525,2600 ; 5475.81,3249.2 cw(c5525.8,3250.01) 5525,3300 ; 5625,865 ccw(c5675,865) 5675,815 ; 5625,1135 cw(c5650,1135) 5650,1160 ; 5660,310 ccw(c5685,310) 5685,285 ; 5660,410 cw(c5685,410) 5685,435 ; 5670,1160 ccw(c5670,1210) 5720,1210 ; 5675,65 ccw(c5700,65) 5700,40 ; 5675,240 cw(c5700,240) 5700,265 ; 5710,285 ccw(c5710,310) 5735,310 cw(c5760,310) 5760,335 ; 5720,1220 cw(c5745,1220) 5745,1245 ; 5724.41,7744.98 cw(c5722,7595) 5871.98,7592.59 ; 5750,265 cw(c5750,240) 5775,240 ; 5780,255 ccw(c5805,255) 5805,230 ; 5780,310 cw(c5805,310) 5805,335 ; 5880,410 cw(c5905,410) 5905,435 ; 5899.2,1244.99 cw(c5900,1195) 5949.99,1195.8 ; 5950,965 ccw(c6000,965) 6000,915 ; 5960,230 ccw(c5960,255) 5985,255 ; 5985,315 cw(c6010,315) 6010,340 ; 5999.2,1897.79 cw(c6000,1847.8) 6049.99,1848.6 ; 5999.2,2597.79 cw(c6000,2547.8) 6049.99,2548.6 ; 5999.2,3297.79 cw(c6000,3247.8) 6049.99,3248.6 ; 6000.81,1679.2 ccw(c6000.01,1729.2) 6050,1730 ; 6000.81,2379.2 ccw(c6000.01,2429.2) 6050,2430 ; 6000.81,3079.2 ccw(c6000.01,3129.2) 6050,3130 ; 6035,340 ccw(c6035,365) 6060,365 ; 6035,435 cw(c6035,410) 6060,410 ; 6092.59,5055.02 ccw(c6095,5205) 6244.98,5202.59 ; 6097.41,7086.98 cw(c6095,6937) 6244.98,6934.59 ; 6405,4870 ccw(c6455,4870) 6455,4820 ; 6405,4955 cw(c6455,4955) 6455,5005 ; 6475,4820 ccw(c6475,4870) 6525,4870 ccw(c6575,4870) 6575,4820 ; 6475,5005 cw(c6475,4955) 6525,4955 cw(c6575,4955) 6575,5005 ; 6595,4820 ccw(c6595,4870) 6645,4870 ; 6595,5005 cw(c6595,4955) 6645,4955 ; 6710,720 cw(c6735,720) 6735,745 ; 6710,1685 ccw(c6735,1685) 6735,1660 ; 6710,1740 cw(c6735,1740) 6735,1765 cw(c6735,1790) 6710,1790 ; 6710,1940 cw(c6735,1940) 6735,1965 cw(c6735,1990) 6710,1990 ; 6710,2045 cw(c6735,2045) 6735,2070 ; 6805,1765 ccw(c6805,1790) 6830,1790 cw(c6855,1790) 6855,1815 ; 6805,1965 cw(c6805,1940) 6830,1940 ccw(c6855,1940) 6855,1915 ; 6857,534 cw(c6882,534) 6882,559 ; 6915,1660 ccw(c6915,1685) 6940,1685 ; 6915,2070 cw(c6915,2045) 6940,2045 ; 6940,1790 ccw(c6915,1790) 6915,1815 ccw(c6915,1840) 6940,1840 ; 6940,1890 ccw(c6915,1890) 6915,1915 ccw(c6915,1940) 6940,1940 ; 7009.2,559.99 cw(c7010,510) 7059.99,510.8 ; 7014.2,559.99 cw(c7015,510) 7064.99,510.8 ; 7035.41,114.6 ccw(c7035,139.6) 7060,140 ; 7065.01,504.2 ccw(c7115,505) 7115.8,455.01 ; 7069.2,809.99 cw(c7070,760) 7119.99,760.8 ; 7078.58,1685 ccw(c7103.58,1685) 7103.58,1660 ; 7078.58,1740 cw(c7103.58,1740) 7103.58,1765 cw(c7103.58,1790) 7078.58,1790 ; 7078.58,1940 cw(c7103.58,1940) 7103.58,1965 cw(c7103.58,1990) 7078.58,1990 ; 7078.58,2045 cw(c7103.58,2045) 7103.58,2070 ; 7120.01,669.2 ccw(c7170,670) 7170.8,620.01 ; 7145,810 ccw(c7145,835) 7170,835 ; 7145,915 cw(c7145,890) 7170,890 ; 7173.58,1765 ccw(c7173.58,1790) 7198.58,1790 cw(c7223.58,1790) 7223.58,1815 ; 7173.58,1965 cw(c7173.58,1940) 7198.58,1940 ccw(c7223.58,1940) 7223.58,1915 ; 7189.2,619.19 cw(c7190,569.2) 7239.99,570 ; 7190.81,454.2 ccw(c7190.01,504.2) 7240,505 ; 7283.58,1660 ccw(c7283.58,1685) 7308.58,1685 ; 7283.58,2070 cw(c7283.58,2045) 7308.58,2045 ; 7308.58,1790 ccw(c7283.58,1790) 7283.58,1815 ccw(c7283.58,1840) 7308.58,1840 ; 7308.58,1890 ccw(c7283.58,1890) 7283.58,1915 ccw(c7283.58,1940) 7308.58,1940 ; 7475,1569.52 ccw(c7505,1570) 7505.48,1540 ; 7475,1814.52 cw(c7505,1815) 7504.52,1845 ; 7475,2184.52 ccw(c7505,2185) 7505.48,2155 ; 7475,2429.52 cw(c7505,2430) 7504.52,2460 ; 7770,1439.52 ccw(c7800,1440) 7800.48,1410 ; 7770,1524.52 cw(c7800,1525) 7799.52,1555 ; 7770,2054.52 ccw(c7800,2055) 7800.48,2025 ; 7770,2139.52 cw(c7800,2140) 7799.52,2170 ; 7785,4320 ccw(c7810,4320) 7810,4295 ; 7785,4505 cw(c7810,4505) 7810,4530 ; 7865,4530 cw(c7865,4505) 7890,4505 ; 7934.2,1844.19 cw(c7935.01,1794.2) 7985,1795 ; 7934.2,2459.19 cw(c7935.01,2409.2) 7985,2410 ; 7935.8,1555.01 ccw(c7935,1605) 7984.99,1605.8 ; 7935.8,2170.01 ccw(c7935,2220) 7984.99,2220.8 ; 7954.52,1555 cw(c7955,1525) 7985,1525.48 ; 7954.52,2170 cw(c7955,2140) 7985,2140.48 ; 7955.48,1410 ccw(c7955,1440) 7985,1440.48 ; 7955.48,2025 ccw(c7955,2055) 7985,2055.48

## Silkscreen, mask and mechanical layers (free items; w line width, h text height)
Top Overlay:
  drawing of 92 lines, arcs and shapes, not listed
  text "+" at 2026.69,7914.65 h250 r180
  text "-" at 4806.69,7914.96 h250 r180
  text "W-" at 6200.02,7585 h60
  text "W+" at 6400.02,7585 h60
  text "V-" at 6600.02,7585 h60
  text "V+" at 6800.02,7585 h60
  text "U-" at 7000.02,7585 h60
  text "U+" at 7200.02,7585 h60
  text "DC+" at 1490.03,7170 h60
  text "DC+" at 2580.03,7170 h60
  text "DC-" at 4270.03,7170 h60
  text "DC-" at 5350.03,7170 h60
  text "H" at 796.88,7026.88 h900
  text "25kW WolfPACK FM3 Six-Pack Inverter / PN CRD25DA12N-FMC, V1.1 07/2023" at 1763.05,5355 h100
  text "(OFF)" at 1888.21,3653 h35
  text "(ON)" at 4966,3653 h35
  text "(G1)" at 2810.03,3650 h60
  text "(G3)" at 3405.03,3650 h60
  text "(G5)" at 4005.03,3650 h60
  text "3.3" at 7546.26,3631 h35
  text "+5" at 7680.84,3631 h35
  text "PWR" at 7514,3555.7 h35 r90
  text "GND" at 7543.35,3531 h35
  text "GND" at 7663.35,3531 h35
  text "(ON)" at 1923.2,3523 h35
  text "(OFF)" at 4966,3523 h35
  text "A14" at 7546.26,3431 h35
  text "C14" at 7666.26,3431 h35
  text "ADC" at 7514,3405.7 h35 r90
  text "35" at 7560.84,3331 h35
  text "44" at 7680.84,3331 h35
  text "GPIO" at 7514,3243.77 h35 r90
  text "54" at 7560.84,3231 h35
  text "55" at 7680.84,3231 h35
  text "GND" at 7543.35,3131 h35
  text "+12" at 7666.26,3131 h35
  text "PWR" at 7514,3105.7 h35 r90
  text "+" at 7750,2960.01 h60 r90
  text "(OFF)" at 1888.21,2953 h35
  text "(ON)" at 4966,2953 h35
  text "-" at 7749.99,2860.01 h60 r90
  text "(ON)" at 1923.2,2823 h35
  text "(OFF)" at 4966,2823 h35
  text "FANS" at 7655,2685.04 h60 r90
  text "+" at 7750,2655.01 h60 r90
  text "-" at 7749.99,2555.01 h60 r90
  text "+3.3V" at 7350,2535 h60
  text "+5V" at 7350,2365 h60
  text "(OFF)" at 1888.21,2253 h35
  text "(ON)" at 4966,2253 h35
  text "2-" at 7625,2250.02 h60 r90
  text "GND" at 7350,2195 h60
  text "(ON)" at 1923.2,2123 h35
  text "(OFF)" at 4966,2123 h35
  text "(G2)" at 2805.03,2050 h60
  text "(G4)" at 3405.03,2050 h60
  text "(G6)" at 4005.03,2050 h60
  text "2+" at 7625,2050.02 h60 r90
  text "RELAYS" at 7530,1725.06 h60 r90
  text "1-" at 7625,1640.01 h60 r90
  text "1+" at 7625,1440.01 h60 r90
  text "+3.3V" at 6250.09,1285 h60
  text "+5V" at 6360.05,1200 h60
  text "+15V" at 6310.07,1115 h60
  text "-15V" at 6310.07,1035 h60
  text "+15V" at 5610,805 h60
  text "U" at 1640.01,685 h60
  text "V" at 3030.01,685 h60
  text "W" at 4420.01,685 h60
  text "-15V" at 5610,665 h60
  text "1" at 7499,534.17 h35 r90
  text "2" at 7564,528.34 h35 r90
  text "GND" at 5610,525 h60
  text "3" at 7499,478.34 h35 r90
  text "4" at 7564,478.34 h35 r90
  text "5" at 7499,428.34 h35 r90
  text "6" at 7564,428.34 h35 r90
  text "-" at 7465,364.99 h60 r180
  text "+12V" at 6555,210 h60
  text "+" at 7465,95 h60 r180
  text "U" at 2026.69,85 h250
  text "V" at 3416.69,85 h250
  text "W" at 4806.69,85 h250
  text "GND" at 6555,65 h60
  text "+12V" at 7496,16 h35
Bottom Overlay:
  lines w8: 6614.61,6089.61 6623.8,6098.8 ; 6974.61,6089.61 6983.8,6098.8 ; 7334.61,6089.61 7343.8,6098.8 ; 7694.61,6089.61 7703.8,6098.8 ; 7880,755 7880,669 7990,669 ; 7885,821 7992,821 7992,669
  lines w10: 6900,4015 6921.3,4036.3 6922.52,4036.3 ; 6900,4288 6921.3,4309.3 ; 6935,1300 6935,1350 ; 7080,1230 7080,1250 ; 7170,745 7185,745 ; 7170,865 7185,865 ; 7225,1230 7225,1250 ; 7315,465 7260,465 7260,635 7420,635 7420,465 7395,465 ; 7380,375 7380,360 7380,265 7525,265 ; 7395,435 7555,435 7555,365 ; 7420,620 7433.22,620 7482.52,669.3 ; 7530,640 7530,665 ; 7555,395 7620.39,460.39 ; 7725,717.5 7874.5,717.5 ; 6580,3900 6900,3900 6900,4020 6580,4020 6580,3900 ; 6580,4183.5 6900,4183.5 6900,4303.5 6580,4303.5 6580,4183.5 ; 6832.5,1350 6997.5,1350 6997.5,1470 6832.5,1470 6832.5,1350 ; 7017.5,1250 7182.5,1250 7182.5,1470 7017.5,1470 7017.5,1250 ; 7050,600 7170,600 7170,765 7050,765 7050,600 ; 7050,780 7170,780 7170,940 7050,940 7050,780 ; 7202.5,1250 7367.5,1250 7367.5,1470 7202.5,1470 7202.5,1250
Board Outline:
  lines w10: 55,-8425 ccw(c55,-8325) 155,-8325 ; 0,100 ccw(c100,100) 100,0 7900,0 ccw(c7900,100) 8000,100 8000,7900 ccw(c7900,7900) 7900,8000 100,8000 ccw(c100,7900) 0,7900 0,100
Drill Drawing:
  drawing of 161 lines, arcs and shapes, not listed
  text "*" at 140,12010 h60
  text "THESE HOLES (1.10MM +/- 0.05MM) ARE FOR PRESS-FIT PART. USE 47.2MIL +/- 1MIL DRILLED HOLES. COPPER THICKNESS IN HOLE 25-50UM." at 235,11955 h100
  text "w" at 9.31,11929.72 h200
  text "^" at 145,11825.01 h60
  text "THESE HOLES (1.48MM +/- 0.05MM) ARE FOR PRESS-FIT PART. USE 63.0MIL +/- 1MIL DRILLED HOLES. COPPER THICKNESS IN HOLE 25-60UM." at 240,11760 h100
  text "w" at 15.85,11741.66 h200
  text "Symbol" at 97.5,11578.94 h72
  text "Count" at 603.38,11578.94 h72
  text "Hole Size" at 1203.22,11578.94 h72
  text "Plated" at 2302.9,11578.94 h72
  text "Hole Type" at 2808.77,11578.94 h72
  text "Drill Layer Pair" at 3542.57,11578.94 h72
  text "Via/Pad" at 5042.13,11578.94 h72
  text "Pad Shape" at 5631.97,11578.94 h72
  text "Hole Tolerance (+)" at 6377.77,11578.94 h72
  text "Hole Tolerance (-)" at 7711.38,11578.94 h72
  text "Hole Length" at 9044.99,11578.94 h72
  text "Routed Path Length" at 10074.69,11578.94 h72
  text "27" at 603.38,11428.94 h60
  text "0.20mm (7.87mil)" at 1203.22,11428.94 h60
  text "PTH" at 2302.9,11428.94 h60
  text "Round" at 2808.77,11428.94 h60
  text "Top Layer - Bottom Layer" at 3542.57,11428.94 h60
  text "Via" at 5042.13,11428.94 h60
  text "Rounded" at 5631.97,11428.94 h60
  text "0.08mm (3.00mil)" at 6377.77,11428.94 h60
  text "0.08mm (3.00mil)" at 7711.38,11428.94 h60
  text "-" at 9044.99,11428.94 h60
  text "-" at 10074.69,11428.94 h60
  text "455" at 603.38,11278.94 h60
  text "0.33mm (13.00mil)" at 1203.22,11278.94 h60
  text "PTH" at 2302.9,11278.94 h60
  text "Round" at 2808.77,11278.94 h60
  text "Top Layer - Bottom Layer" at 3542.57,11278.94 h60
  text "Via" at 5042.13,11278.94 h60
  text "Rounded" at 5631.97,11278.94 h60
  text "0.08mm (3.00mil)" at 6377.77,11278.94 h60
  text "0.08mm (3.00mil)" at 7711.38,11278.94 h60
  text "-" at 9044.99,11278.94 h60
  text "-" at 10074.69,11278.94 h60
  text "A" at 68.41,11268.95 h66.67
  text "76" at 603.38,11128.94 h60
  text "0.71mm (28.00mil)" at 1203.22,11128.94 h60
  text "PTH" at 2302.9,11128.94 h60
  text "Round" at 2808.77,11128.94 h60
  text "Top Layer - Bottom Layer" at 3542.57,11128.94 h60
  text "Via" at 5042.13,11128.94 h60
  text "Rounded" at 5631.97,11128.94 h60
  text "0.08mm (3.00mil)" at 6377.77,11128.94 h60
  text "0.08mm (3.00mil)" at 7711.38,11128.94 h60
  text "-" at 9044.99,11128.94 h60
  text "-" at 10074.69,11128.94 h60
  text "32" at 603.38,10978.94 h60
  text "0.84mm (33.07mil)" at 1203.22,10978.94 h60
  text "PTH" at 2302.9,10978.94 h60
  text "Round" at 2808.77,10978.94 h60
  text "Top Layer - Bottom Layer" at 3542.57,10978.94 h60
  text "Pad" at 5042.13,10978.94 h60
  text "(Mixed)" at 5631.97,10978.94 h60
  text "0.08mm (3.00mil)" at 6377.77,10978.94 h60
  text "0.08mm (3.00mil)" at 7711.38,10978.94 h60
  text "-" at 9044.99,10978.94 h60
  text "-" at 10074.69,10978.94 h60
  text "18" at 603.38,10828.94 h60
  text "1.00mm (39.37mil)" at 1203.22,10828.94 h60
  text "PTH" at 2302.9,10828.94 h60
  text "Round" at 2808.77,10828.94 h60
  text "Top Layer - Bottom Layer" at 3542.57,10828.94 h60
  text "Pad" at 5042.13,10828.94 h60
  text "(Mixed)" at 5631.97,10828.94 h60
  text "0.08mm (3.00mil)" at 6377.77,10828.94 h60
  text "0.08mm (3.00mil)" at 7711.38,10828.94 h60
  text "-" at 9044.99,10828.94 h60
  text "-" at 10074.69,10828.94 h60
  text "3" at 603.38,10678.94 h60
  text "1.00mm (39.37mil)" at 1203.22,10678.94 h60
  text "PTH" at 2302.9,10678.94 h60
  text "Slot" at 2808.77,10678.94 h60
  text "Top Layer - Bottom Layer" at 3542.57,10678.94 h60
  text "Pad" at 5042.13,10678.94 h60
  text "Rectangle" at 5631.97,10678.94 h60
  text "0.08mm (3.00mil)" at 6377.77,10678.94 h60
  text "0.08mm (3.00mil)" at 7711.38,10678.94 h60
  text "1.60mm (62.99mil)" at 9044.99,10678.94 h60
  text "0.60mm (23.62mil)" at 10074.69,10678.94 h60
  text "B" at 68.41,10668.95 h66.67
  text "18" at 603.38,10528.94 h60
  text "1.10mm (43.31mil)" at 1203.22,10528.94 h60
  text "PTH" at 2302.9,10528.94 h60
  text "Round" at 2808.77,10528.94 h60
  text "Top Layer - Bottom Layer" at 3542.57,10528.94 h60
  text "Pad" at 5042.13,10528.94 h60
  text "(Mixed)" at 5631.97,10528.94 h60
  text "0.08mm (3.00mil)" at 6377.77,10528.94 h60
  text "0.08mm (3.00mil)" at 7711.38,10528.94 h60
  text "-" at 9044.99,10528.94 h60
  text "-" at 10074.69,10528.94 h60
  text "D" at 68.41,10518.95 h66.67
  text "*" at -85,10430 h60
  text "23" at 603.38,10378.94 h60
  text "1.10mm (43.31mil)" at 1203.22,10378.94 h60
  text "PTH" at 2302.9,10378.94 h60
  text "Round" at 2808.77,10378.94 h60
  text "Top Layer - Bottom Layer" at 3542.57,10378.94 h60
  text "Pad" at 5042.13,10378.94 h60
  text "Rounded" at 5631.97,10378.94 h60
  text "0.05mm (1.97mil)" at 6377.77,10378.94 h60
  text "0.05mm (1.97mil)" at 7711.38,10378.94 h60
  text "-" at 9044.99,10378.94 h60
  text "-" at 10074.69,10378.94 h60
  text "w" at -215.69,10349.72 h200
  text "30" at 603.38,10228.94 h60
  text "1.15mm (45.28mil)" at 1203.22,10228.94 h60
  text "PTH" at 2302.9,10228.94 h60
  text "Round" at 2808.77,10228.94 h60
  text "Top Layer - Bottom Layer" at 3542.57,10228.94 h60
  text "Pad" at 5042.13,10228.94 h60
  text "Rounded" at 5631.97,10228.94 h60
  text "0.08mm (3.00mil)" at 6377.77,10228.94 h60
  text "0.08mm (3.00mil)" at 7711.38,10228.94 h60
  text "-" at 9044.99,10228.94 h60
  text "-" at 10074.69,10228.94 h60
  text "9" at 603.38,10078.94 h60
  text "1.20mm (47.24mil)" at 1203.22,10078.94 h60
  text "PTH" at 2302.9,10078.94 h60
  text "Round" at 2808.77,10078.94 h60
  text "Top Layer - Bottom Layer" at 3542.57,10078.94 h60
  text "Pad" at 5042.13,10078.94 h60
  text "Rounded" at 5631.97,10078.94 h60
  text "0.08mm (3.00mil)" at 6377.77,10078.94 h60
  text "0.08mm (3.00mil)" at 7711.38,10078.94 h60
  text "-" at 9044.99,10078.94 h60
  text "-" at 10074.69,10078.94 h60
  text "2" at 603.38,9928.94 h60
  text "1.27mm (50.00mil)" at 1203.22,9928.94 h60
  text "NPTH" at 2302.9,9928.94 h60
  text "Round" at 2808.77,9928.94 h60
  text "Top Layer - Bottom Layer" at 3542.57,9928.94 h60
  text "Pad" at 5042.13,9928.94 h60
  text "Rounded" at 5631.97,9928.94 h60
  text "0.08mm (3.00mil)" at 6377.77,9928.94 h60
  text "0.08mm (3.00mil)" at 7711.38,9928.94 h60
  text "-" at 9044.99,9928.94 h60
  text "-" at 10074.69,9928.94 h60
  text "4" at 603.38,9778.94 h60
  text "1.30mm (51.18mil)" at 1203.22,9778.94 h60
  text "PTH" at 2302.9,9778.94 h60
  text "Round" at 2808.77,9778.94 h60
  text "Top Layer - Bottom Layer" at 3542.57,9778.94 h60
  text "Pad" at 5042.13,9778.94 h60
  text "(Mixed)" at 5631.97,9778.94 h60
  text "0.08mm (3.00mil)" at 6377.77,9778.94 h60
  text "0.08mm (3.00mil)" at 7711.38,9778.94 h60
  text "-" at 9044.99,9778.94 h60
  text "-" at 10074.69,9778.94 h60
  text "C" at 68.41,9768.95 h66.67
  text "10" at 603.38,9628.94 h60
  text "1.40mm (55.12mil)" at 1203.22,9628.94 h60
  text "PTH" at 2302.9,9628.94 h60
  text "Round" at 2808.77,9628.94 h60
  text "Top Layer - Bottom Layer" at 3542.57,9628.94 h60
  text "Pad" at 5042.13,9628.94 h60
  text "(Mixed)" at 5631.97,9628.94 h60
  text "0.08mm (3.00mil)" at 6377.77,9628.94 h60
  text "0.08mm (3.00mil)" at 7711.38,9628.94 h60
  text "-" at 9044.99,9628.94 h60
  text "-" at 10074.69,9628.94 h60
  text "^" at -100,9525.01 h60
  text "40" at 603.38,9478.94 h60
  text "1.48mm (58.07mil)" at 1203.22,9478.94 h60
  text "PTH" at 2302.9,9478.94 h60
  text "Round" at 2808.77,9478.94 h60
  text "Top Layer - Bottom Layer" at 3542.57,9478.94 h60
  text "Pad" at 5042.13,9478.94 h60
  text "Rounded" at 5631.97,9478.94 h60
  text "0.05mm (1.97mil)" at 6377.77,9478.94 h60
  text "0.05mm (1.97mil)" at 7711.38,9478.94 h60
  text "-" at 9044.99,9478.94 h60
  text "-" at 10074.69,9478.94 h60
  text "E" at 68.41,9468.95 h66.67
  text "w" at -229.15,9441.66 h200
  text "15" at 603.38,9328.94 h60
  text "1.60mm (62.99mil)" at 1203.22,9328.94 h60
  text "PTH" at 2302.9,9328.94 h60
  text "Round" at 2808.77,9328.94 h60
  text "Top Layer - Bottom Layer" at 3542.57,9328.94 h60
  text "Pad" at 5042.13,9328.94 h60
  text "Rounded" at 5631.97,9328.94 h60
  text "0.08mm (3.00mil)" at 6377.77,9328.94 h60
  text "0.08mm (3.00mil)" at 7711.38,9328.94 h60
  text "-" at 9044.99,9328.94 h60
  text "-" at 10074.69,9328.94 h60
  text "30" at 603.38,9178.94 h60
  text "2.00mm (78.74mil)" at 1203.22,9178.94 h60
  text "PTH" at 2302.9,9178.94 h60
  text "Round" at 2808.77,9178.94 h60
  text "Top Layer - Bottom Layer" at 3542.57,9178.94 h60
  text "Pad" at 5042.13,9178.94 h60
  text "Rounded" at 5631.97,9178.94 h60
  text "0.08mm (3.00mil)" at 6377.77,9178.94 h60
  text "0.08mm (3.00mil)" at 7711.38,9178.94 h60
  text "-" at 9044.99,9178.94 h60
  text "-" at 10074.69,9178.94 h60
  text "2" at 603.38,9028.94 h60
  text "3.05mm (120.08mil)" at 1203.22,9028.94 h60
  text "PTH" at 2302.9,9028.94 h60
  text "Round" at 2808.77,9028.94 h60
  text "Top Layer - Bottom Layer" at 3542.57,9028.94 h60
  text "Pad" at 5042.13,9028.94 h60
  text "Rounded" at 5631.97,9028.94 h60
  text "0.13mm (5.00mil)" at 6377.77,9028.94 h60
  text "0.13mm (5.00mil)" at 7711.38,9028.94 h60
  text "-" at 9044.99,9028.94 h60
  text "-" at 10074.69,9028.94 h60
  text "8" at 603.38,8878.94 h60
  text "4.50mm (177.17mil)" at 1203.22,8878.94 h60
  text "PTH" at 2302.9,8878.94 h60
  text "Round" at 2808.77,8878.94 h60
  text "Top Layer - Bottom Layer" at 3542.57,8878.94 h60
  text "Pad" at 5042.13,8878.94 h60
  text "Rounded" at 5631.97,8878.94 h60
  text "0.13mm (5.00mil)" at 6377.77,8878.94 h60
  text "0.13mm (5.00mil)" at 7711.38,8878.94 h60
  text "-" at 9044.99,8878.94 h60
  text "-" at 10074.69,8878.94 h60
  text "2" at 603.38,8728.94 h60
  text "9.00mm (354.33mil)" at 1203.22,8728.94 h60
  text "NPTH" at 2302.9,8728.94 h60
  text "Round" at 2808.77,8728.94 h60
  text "Top Layer - Bottom Layer" at 3542.57,8728.94 h60
  text "Pad" at 5042.13,8728.94 h60
  text "Rounded" at 5631.97,8728.94 h60
  text "0.13mm (5.00mil)" at 6377.77,8728.94 h60
  text "0.13mm (5.00mil)" at 7711.38,8728.94 h60
  text "-" at 9044.99,8728.94 h60
  text "-" at 10074.69,8728.94 h60
  text "F" at 68.41,8718.95 h66.67
  text "804 Total" at 603.38,8578.94 h60
  text "Slot definitions :" at 97.5,8433.97 h60
  text "Routed Path Length" at 1130.19,8433.97 h60
  text "= Calculated from tool start centre position to tool end centre position." at 2232.86,8433.97 h60
  text "Hole Length" at 1130.19,8333.99 h60
  text "= Routed Path Length + Tool Size = Slot length as defined in the PCB layout" at 1822.99,8333.99 h60

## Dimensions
100,8000 to 100,0 on Drill Drawing
0,100 to 8000,100 on Drill Drawing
